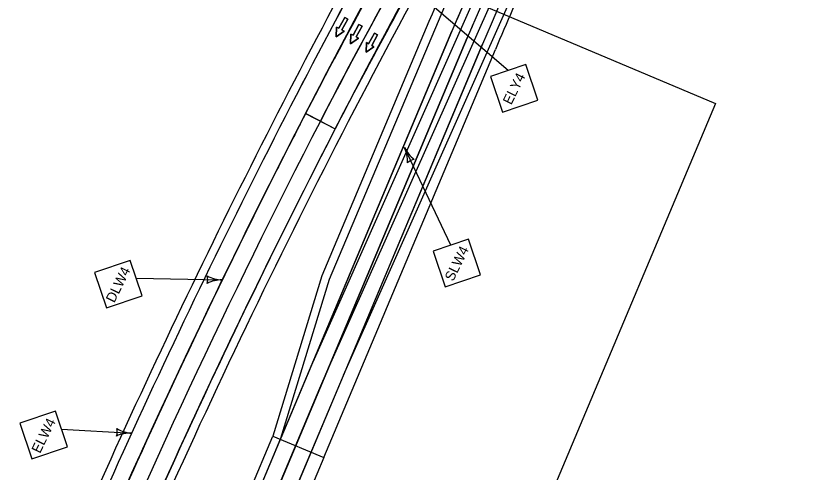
# Model space of a CAD drawing. Extents: x 14104283 to 14120882, y 8635219 to 8671666.
# Drawn here: x 14118626 to 14119195, y 8668145 to 8668473 of the extents above; entities that cross this region are included whole.
import ezdxf

# ---------------------------------------------------------------- set-up
doc = ezdxf.new("R2010")
doc.units = 0
for name, color, linetype in [('dsnNonPlotable', 7, 'Continuous'), ('dsnPaintExistingEdgeLineLeftYellow', 7, 'Continuous'), ('dsnPaintExistingEdgeLineRightWhite', 7, 'Continuous'), ('dsnPaintExistingLaneLineWhite', 7, 'Continuous'), ('dsnPaintPlaceBrokenLineWhite', 7, 'Continuous'), ('dsnPaintPlaceDottedLineWhite', 7, 'Continuous'), ('dsnPaintPlaceEdgeLineLeftYellow', 7, 'Continuous'), ('dsnPaintPlaceEdgeLineRightWhite', 7, 'Continuous'), ('dsnPaintPlaceLaneLineWhite', 7, 'Continuous'), ('dsnPaintRemoveDoubleCenterLineYellow', 7, 'Continuous'), ('dsnShadingPaved', 7, 'Continuous'), ('dsnStdLabel', 7, 'Continuous'), ('dsnStgShadingPrevPav', 7, 'Continuous'), ('dsnTapePlaceChannelizingLaneWhite', 7, 'Continuous'), ('dsnTapePlaceEdgeLineLeftYellow', 7, 'Continuous'), ('dsnTapeRemoveChannelizingWhite', 7, 'Continuous'), ('dsnTapeRemoveDoubleCenterLineYellow', 7, 'Continuous'), ('Level 2', 7, 'Continuous'), ('Level 5', 7, 'Continuous')]:
    doc.layers.add(name, color=color, linetype=linetype)

msp = doc.modelspace()

# ---------------------------------------------------------------- linework, layer by layer
at = {"layer": 'dsnNonPlotable'}
msp.add_lwpolyline([(14118056.48, 8667161.91), (14118665.06, 8668606.45), (14119130.44, 8668410.38), (14118521.87, 8666965.84)], close=True, dxfattribs=at)
at = {"layer": 'dsnPaintExistingEdgeLineLeftYellow'}
for p, q in [((14118852.57, 8668283.93), (14118948.15, 8668509.94)), ((14118817.44, 8668169.6), (14118852.57, 8668283.93))]:
    msp.add_line(p, q, dxfattribs=at)
at = {"layer": 'dsnPaintExistingEdgeLineRightWhite'}
for p, q in [((14118862.46, 8668214.66), (14118962.79, 8668452.92)), ((14110924.38, 8649364.51), (14118862.46, 8668214.66))]:
    msp.add_line(p, q, dxfattribs=at)
at = {"layer": 'dsnPaintExistingLaneLineWhite'}
msp.add_arc((14121592.11, 8667345.68), 2876.95, 153.70867, 157.1633, dxfattribs=at)
at = {"layer": 'dsnPaintPlaceBrokenLineWhite'}
msp.add_line((14114932.53, 8658913.38), (14118951.74, 8668457.58), dxfattribs=at)
for centre, radius, start, end in [((14121592.11, 8667345.68), 2864.95, 147.15737, 157.1633), ((14121955.85, 8666791.92), 3500, 149.50762, 152.69211), ((14123732.96, 8665874.38), 5500, 152.69211, 157.1633)]:
    msp.add_arc(centre, radius, start, end, dxfattribs=at)
at = {"layer": 'dsnPaintPlaceDottedLineWhite'}
msp.add_arc((14123732.96, 8665874.38), 5512, 152.23375, 154.51073, dxfattribs=at)
at = {"layer": 'dsnPaintPlaceEdgeLineLeftYellow'}
msp.add_line((14115900.95, 8661243.95), (14118817.44, 8668169.6), dxfattribs=at)
at = {"layer": 'dsnPaintPlaceEdgeLineRightWhite'}
for centre, radius, start, end in [((14121592.11, 8667345.68), 2852.95, 147.15737, 157.1633), ((14123732.96, 8665874.38), 5524, 150.3689, 156.09858)]:
    msp.add_arc(centre, radius, start, end, dxfattribs=at)
at = {"layer": 'dsnPaintPlaceLaneLineWhite'}
msp.add_line((14118863.63, 8668279.27), (14118940.68, 8668462.24), dxfattribs=at)
msp.add_arc((14122745.39, 8666422.79), 4382.73, 149.34837, 152.56312, dxfattribs=at)
at = {"layer": 'dsnPaintRemoveDoubleCenterLineYellow'}
msp.add_lwpolyline([(14118766.99, 8668018.87), (14118845.58, 8668205.49), (14118851.47, 8668219.49)], dxfattribs=at)
at = {"layer": 'dsnShadingPaved'}
for p, q in [((14118852.57, 8668283.93), (14118948.15, 8668509.94)), ((14118227.72, 8666769.23), (14118940.68, 8668462.24)), ((14118940.68, 8668462.24), (14118817.44, 8668169.6)), ((14118962.79, 8668452.92), (14118249.84, 8666759.92)), ((14118845.91, 8668397.62), (14118835.25, 8668403.13)), ((14118835.25, 8668403.13), (14118856.57, 8668392.12)), ((14118845.91, 8668397.62), (14118856.57, 8668392.12)), ((14118817.44, 8668169.6), (14118852.57, 8668283.93))]:
    msp.add_line(p, q, dxfattribs=at)
for centre, radius, start, end in [((14121592.11, 8667345.68), 2876.95, 147.15737, 157.1633), ((14121592.11, 8667345.68), 2852.95, 147.15737, 157.1633), ((14121955.85, 8666791.92), 3512, 144.95493, 152.69211), ((14121955.85, 8666791.92), 3500, 144.95493, 152.69211), ((14121592.11, 8667345.68), 2876.95, 151.25989, 157.1633), ((14123732.96, 8665874.38), 5512, 149.67774, 156.09858), ((14123732.96, 8665874.38), 5524, 150.3689, 153.23374), ((14121955.85, 8666791.92), 3500, 149.50762, 152.69211), ((14121955.85, 8666791.92), 3488, 151.15555, 152.69211), ((14123732.96, 8665874.38), 5512, 152.69211, 153.16925), ((14123732.96, 8665874.38), 5488, 152.69211, 157.1633), ((14123732.96, 8665874.38), 5512, 153.16925, 157.1633), ((14123732.96, 8665874.38), 5524, 153.23374, 156.09858)]:
    msp.add_arc(centre, radius, start, end, dxfattribs=at)
at = {"layer": 'dsnStdLabel'}
for p, q in [((14118981.16, 8668434.03), (14118911.62, 8668493.66)), ((14118951.74, 8668457.58), (14118742.16, 8667959.91)), ((14118939.92, 8668308.3), (14118906.49, 8668378.58)), ((14118713.06, 8668284.65), (14118775.15, 8668283.41)), ((14118659.37, 8668176.04), (14118709.96, 8668173.09))]:
    msp.add_line(p, q, dxfattribs=at)
for points in [[(14118977.03, 8668404.12), (14119002.6, 8668412.78), (14118993.95, 8668438.35), (14118968.38, 8668429.7)], [(14118935.79, 8668278.4), (14118961.36, 8668287.05), (14118952.71, 8668312.63), (14118927.13, 8668303.97)], [(14118691.81, 8668263.21), (14118717.39, 8668271.86), (14118708.74, 8668297.43), (14118683.16, 8668288.78)], [(14118638.12, 8668154.6), (14118663.69, 8668163.26), (14118655.04, 8668188.83), (14118629.46, 8668180.18)]]:
    msp.add_lwpolyline(points, close=True, dxfattribs=at)
for centre, radius, start, end in [((14121598.52, 8667342.84), 2871.95, 156.90153, 157.16083), ((14118885.76, 8668368.73), 22.95, 357.3688, 25.4401), ((14118927.21, 8668388.44), 22.95, 205.4399, 233.5112), ((14118914.75, 8668361.21), 8.86, 97.7057, 133.1742), ((14118755.91, 8668283.55), 8.86, 341.8404, 17.3088), ((14118775.32, 8668306.36), 22.95, 241.5034, 269.5747), ((14118774.98, 8668260.46), 22.95, 89.5745, 117.6458), ((14118690.75, 8668174.21), 8.86, 338.925, 14.3935), ((14118711.3, 8668196), 22.95, 238.5881, 266.6594), ((14118708.62, 8668150.18), 22.95, 86.6592, 114.7305)]:
    msp.add_arc(centre, radius, start, end, dxfattribs=at)
at = {"layer": 'dsnStgShadingPrevPav'}
for p, q in [((14118924.09, 8668469.22), (14118847.04, 8668286.26)), ((14118848.39, 8668155.49), (14118972.01, 8668449.04)), ((14118847.04, 8668286.26), (14118811.53, 8668171.01)), ((14115895.65, 8661246.83), (14118811.53, 8668171.01)), ((14118811.53, 8668171.01), (14118848.39, 8668155.49)), ((14118811.53, 8668171.01), (14118848.39, 8668155.49)), ((14118848.39, 8668155.49), (14115932.51, 8661231.3))]:
    msp.add_line(p, q, dxfattribs=at)
for centre, radius, start, end in [((14123732.96, 8665874.38), 5512, 146.42562, 157.1633), ((14123732.96, 8665874.38), 5488, 146.42119, 157.1633), ((14123732.96, 8665874.38), 5530, 150.3689, 156.09911), ((14123732.96, 8665874.38), 5524, 150.3689, 156.09858), ((14123732.96, 8665874.38), 5524, 150.3689, 156.09858), ((14123732.59, 8665873.82), 5512, 150.36196, 157.1633), ((14123732.96, 8665874.38), 5482, 150.67101, 157.1633), ((14123732.96, 8665874.38), 5488, 151.14296, 157.1633), ((14121592.11, 8667345.68), 2894.95, 156.23384, 157.1633), ((14121592.11, 8667345.68), 2842.95, 155.90343, 157.1633)]:
    msp.add_arc(centre, radius, start, end, dxfattribs=at)
at = {"layer": 'dsnTapePlaceChannelizingLaneWhite'}
msp.add_arc((14121955.85, 8666791.92), 3512, 147.96378, 151.97273, dxfattribs=at)
at = {"layer": 'dsnTapePlaceEdgeLineLeftYellow'}
for centre, radius, start, end in [((14121955.85, 8666791.92), 3488, 149.50762, 152.69211), ((14123732.96, 8665874.38), 5488, 152.69211, 157.1633)]:
    msp.add_arc(centre, radius, start, end, dxfattribs=at)
at = {"layer": 'dsnTapeRemoveChannelizingWhite'}
for p, q in [((14118962.39, 8668498.19), (14118840.41, 8668224.15)), ((14118862.53, 8668214.84), (14118984.08, 8668487.9))]:
    msp.add_line(p, q, dxfattribs=at)
at = {"layer": 'dsnTapeRemoveDoubleCenterLineYellow'}
msp.add_line((14118851.47, 8668219.49), (14118987.82, 8668525.18), dxfattribs=at)
at = {"layer": 'Level 2'}
for points in [[(14118865.67, 8668470.86), (14118863.48, 8668472.06), (14118859.26, 8668464.4), (14118857.61, 8668465.3), (14118857.34, 8668458.32), (14118863.09, 8668462.29), (14118861.45, 8668463.19)], [(14118875.9, 8668465.8), (14118873.71, 8668467), (14118869.49, 8668459.34), (14118867.85, 8668460.24), (14118867.57, 8668453.26), (14118873.33, 8668457.23), (14118871.68, 8668458.13)], [(14118887.09, 8668459.71), (14118884.9, 8668460.92), (14118880.67, 8668453.25), (14118879.03, 8668454.16), (14118878.76, 8668447.18), (14118884.51, 8668451.14), (14118882.86, 8668452.05)]]:
    msp.add_lwpolyline(points, close=True, dxfattribs=at)
at = {"layer": 'Level 5'}
for points in [[(14118861.45, 8668463.19), (14118863.09, 8668462.29), (14118857.34, 8668458.32), (14118857.61, 8668465.3), (14118859.26, 8668464.4), (14118863.48, 8668472.06), (14118865.67, 8668470.86), (14118861.45, 8668463.19)], [(14118871.68, 8668458.13), (14118873.33, 8668457.23), (14118867.57, 8668453.26), (14118867.85, 8668460.24), (14118869.49, 8668459.34), (14118873.71, 8668467), (14118875.9, 8668465.8), (14118871.68, 8668458.13)], [(14118882.86, 8668452.05), (14118884.51, 8668451.14), (14118878.76, 8668447.18), (14118879.03, 8668454.16), (14118880.67, 8668453.25), (14118884.9, 8668460.92), (14118887.09, 8668459.71), (14118882.86, 8668452.05)]]:
    msp.add_lwpolyline(points, dxfattribs=at)

# ---------------------------------------------------------------- texts
at = {"layer": 'dsnStdLabel'}
for s, p in [('ELY4', (14118983.37, 8668408.83)), ('SLW4', (14118941.51, 8668281.86)), ('DLW4', (14118697.42, 8668266.42)), ('ELW4', (14118643.84, 8668158.06))]:
    msp.add_text(s, height=7.2, rotation=63.6912, dxfattribs=at).set_placement(p)

doc.saveas('drawing.dxf')
